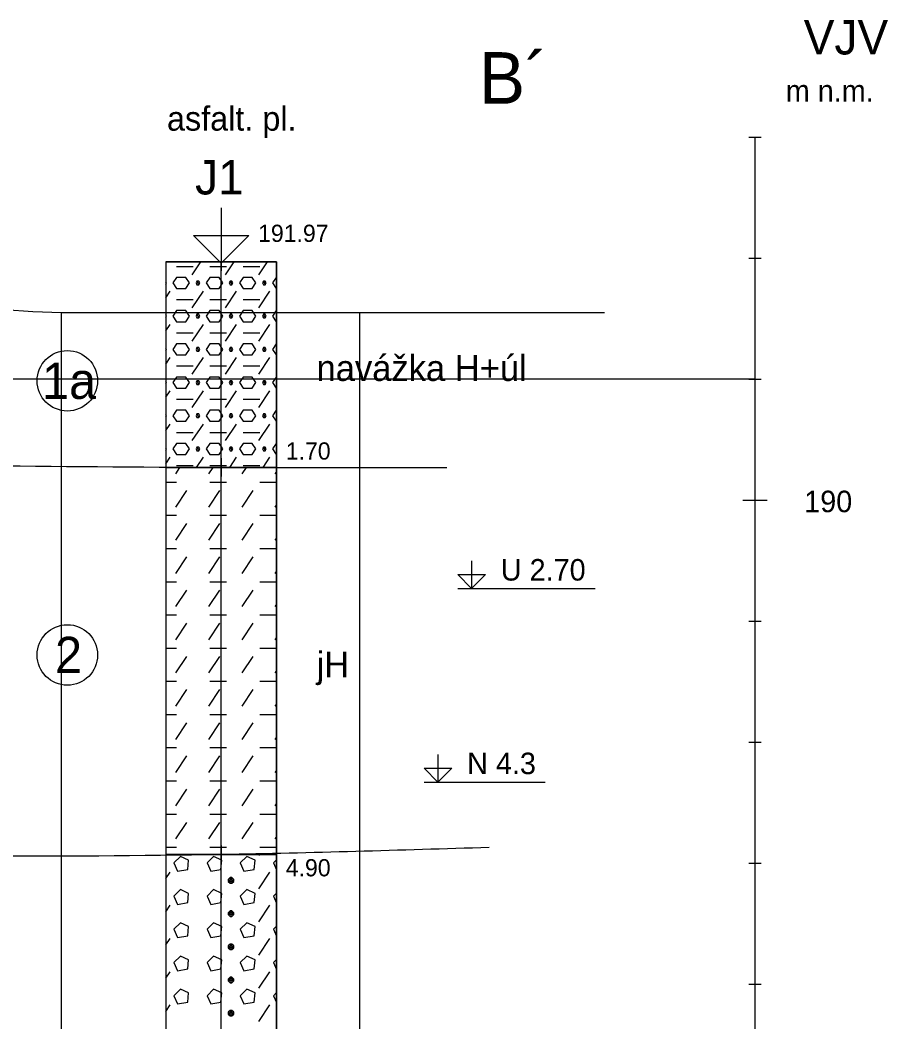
# Model space of a CAD drawing. Extents: x 3042 to 4120, y 576 to 2694.
# Drawn here: x 3544.48 to 3580.33, y 1143.21 to 1184.62 of the extents above; entities that cross this region are included whole.
import ezdxf

# ---------------------------------------------------------------- set-up
doc = ezdxf.new("R2010")
doc.units = 0
for name, color, linetype in [('15', 7, 'Continuous'), ('16', 7, 'Continuous'), ('17', 7, 'Continuous'), ('18', 7, 'Continuous'), ('19', 7, 'Continuous'), ('20', 7, 'Continuous'), ('21', 7, 'Continuous'), ('51', 7, 'Continuous'), ('52', 7, 'Continuous'), ('53', 7, 'Continuous'), ('56', 7, 'Continuous'), ('61', 7, 'Continuous'), ('ig vrty popis', 7, 'Continuous'), ('komunikace', 7, 'Continuous'), ('pomocna', 7, 'Continuous'), ('rozhraní', 7, 'Continuous')]:
    doc.layers.add(name, color=color, linetype=linetype)

msp = doc.modelspace()

# ---------------------------------------------------------------- linework, layer by layer
at = {"layer": '15'}
msp.add_lwpolyline([(3552.792, 1176.852), (3552.792, 1174.566), (3551.649, 1175.709), (3553.935, 1175.709), (3552.792, 1174.566)], dxfattribs=at)
at = {"layer": '18'}
msp.add_line((3552.792, 1134.629), (3552.792, 1174.629), dxfattribs=at)
at = {"layer": '19'}
for p, q in [((3574.588, 1179.779), (3575.096, 1179.779)), ((3574.588, 1174.779), (3575.096, 1174.779)), ((3574.588, 1169.779), (3575.096, 1169.779)), ((3574.334, 1164.779), (3575.35, 1164.779)), ((3574.588, 1159.779), (3575.096, 1159.779)), ((3574.588, 1154.779), (3575.096, 1154.779)), ((3574.588, 1149.779), (3575.096, 1149.779)), ((3574.588, 1144.779), (3575.096, 1144.779))]:
    msp.add_line(p, q, dxfattribs=at)
at = {"layer": '21'}
msp.add_line((3574.842, 1114.779), (3574.842, 1179.779), dxfattribs=at)
at = {"layer": '51'}
for p, q in [((3551.598, 1174.093), (3551.955, 1174.629)), ((3552.97, 1174.093), (3553.327, 1174.629)), ((3554.342, 1174.093), (3554.699, 1174.629)), ((3550.951, 1174.436), (3551.636, 1174.436)), ((3552.322, 1174.436), (3553.008, 1174.436)), ((3553.694, 1174.436), (3554.38, 1174.436)), ((3555.065, 1174.436), (3555.078, 1174.436)), ((3550.506, 1173.14), (3550.684, 1173.408)), ((3551.598, 1172.722), (3552.055, 1173.408)), ((3552.97, 1172.722), (3553.427, 1173.408)), ((3554.342, 1172.722), (3554.799, 1173.408)), ((3555.065, 1173.522), (3555.078, 1173.522)), ((3550.951, 1173.065), (3551.636, 1173.065)), ((3552.322, 1173.065), (3553.008, 1173.065)), ((3553.694, 1173.065), (3554.38, 1173.065)), ((3555.065, 1173.065), (3555.078, 1173.065)), ((3555.065, 1172.15), (3555.078, 1172.15)), ((3550.506, 1171.769), (3550.684, 1172.036)), ((3550.951, 1171.693), (3551.636, 1171.693)), ((3551.598, 1171.35), (3552.055, 1172.036)), ((3552.322, 1171.693), (3553.008, 1171.693)), ((3552.97, 1171.35), (3553.427, 1172.036)), ((3553.694, 1171.693), (3554.38, 1171.693)), ((3554.342, 1171.35), (3554.799, 1172.036)), ((3555.065, 1171.693), (3555.078, 1171.693)), ((3550.506, 1170.397), (3550.684, 1170.664)), ((3551.598, 1169.979), (3552.055, 1170.664)), ((3552.97, 1169.979), (3553.427, 1170.664)), ((3554.342, 1169.979), (3554.799, 1170.664)), ((3555.065, 1170.779), (3555.078, 1170.779)), ((3550.951, 1170.322), (3551.636, 1170.322)), ((3552.322, 1170.322), (3553.008, 1170.322)), ((3553.694, 1170.322), (3554.38, 1170.322)), ((3555.065, 1170.322), (3555.078, 1170.322)), ((3550.506, 1169.026), (3550.684, 1169.293)), ((3551.598, 1168.607), (3552.055, 1169.293)), ((3552.97, 1168.607), (3553.427, 1169.293)), ((3554.342, 1168.607), (3554.799, 1169.293)), ((3555.065, 1169.407), (3555.078, 1169.407)), ((3550.951, 1168.95), (3551.636, 1168.95)), ((3552.322, 1168.95), (3553.008, 1168.95)), ((3553.694, 1168.95), (3554.38, 1168.95)), ((3555.065, 1168.95), (3555.078, 1168.95)), ((3555.065, 1168.036), (3555.078, 1168.036)), ((3550.506, 1167.654), (3550.684, 1167.921)), ((3550.951, 1167.578), (3551.636, 1167.578)), ((3551.598, 1167.235), (3552.055, 1167.921)), ((3552.322, 1167.578), (3553.008, 1167.578)), ((3552.97, 1167.235), (3553.427, 1167.921)), ((3553.694, 1167.578), (3554.38, 1167.578)), ((3554.342, 1167.235), (3554.799, 1167.921)), ((3555.065, 1167.578), (3555.078, 1167.578)), ((3550.506, 1166.282), (3550.684, 1166.55)), ((3551.775, 1166.129), (3552.055, 1166.55)), ((3553.147, 1166.129), (3553.427, 1166.55)), ((3554.518, 1166.129), (3554.799, 1166.55)), ((3555.065, 1166.664), (3555.078, 1166.664)), ((3550.912, 1165.864), (3551.089, 1166.129)), ((3550.951, 1166.207), (3551.636, 1166.207)), ((3552.284, 1165.864), (3552.461, 1166.129)), ((3552.322, 1166.207), (3553.008, 1166.207)), ((3553.656, 1165.864), (3553.833, 1166.129)), ((3553.694, 1166.207), (3554.38, 1166.207)), ((3555.027, 1165.864), (3555.078, 1165.939)), ((3555.065, 1166.207), (3555.078, 1166.207)), ((3550.506, 1165.521), (3550.951, 1165.521)), ((3552.322, 1165.521), (3553.008, 1165.521)), ((3554.38, 1165.521), (3555.065, 1165.521)), ((3550.912, 1164.492), (3551.37, 1165.178)), ((3552.284, 1164.492), (3552.741, 1165.178)), ((3553.656, 1164.492), (3554.113, 1165.178)), ((3555.027, 1164.492), (3555.078, 1164.568)), ((3550.506, 1164.149), (3550.951, 1164.149)), ((3552.322, 1164.149), (3553.008, 1164.149)), ((3554.38, 1164.149), (3555.065, 1164.149)), ((3550.912, 1163.121), (3551.37, 1163.806)), ((3552.284, 1163.121), (3552.741, 1163.806)), ((3553.656, 1163.121), (3554.113, 1163.806)), ((3555.027, 1163.121), (3555.078, 1163.196)), ((3550.506, 1162.778), (3550.951, 1162.778)), ((3552.322, 1162.778), (3553.008, 1162.778)), ((3554.38, 1162.778), (3555.065, 1162.778)), ((3550.912, 1161.749), (3551.37, 1162.435)), ((3552.284, 1161.749), (3552.741, 1162.435)), ((3553.656, 1161.749), (3554.113, 1162.435)), ((3555.027, 1161.749), (3555.078, 1161.825)), ((3550.506, 1161.406), (3550.951, 1161.406)), ((3552.322, 1161.406), (3553.008, 1161.406)), ((3554.38, 1161.406), (3555.065, 1161.406)), ((3550.912, 1160.377), (3551.37, 1161.063)), ((3552.284, 1160.377), (3552.741, 1161.063)), ((3553.656, 1160.377), (3554.113, 1161.063)), ((3555.027, 1160.377), (3555.078, 1160.453)), ((3550.506, 1160.035), (3550.951, 1160.035)), ((3550.912, 1159.006), (3551.37, 1159.692)), ((3552.284, 1159.006), (3552.741, 1159.692)), ((3552.322, 1160.035), (3553.008, 1160.035)), ((3553.656, 1159.006), (3554.113, 1159.692)), ((3554.38, 1160.035), (3555.065, 1160.035)), ((3555.027, 1159.006), (3555.078, 1159.081)), ((3550.506, 1158.663), (3550.951, 1158.663)), ((3552.322, 1158.663), (3553.008, 1158.663)), ((3554.38, 1158.663), (3555.065, 1158.663)), ((3550.912, 1157.634), (3551.37, 1158.32)), ((3552.284, 1157.634), (3552.741, 1158.32)), ((3553.656, 1157.634), (3554.113, 1158.32)), ((3555.027, 1157.634), (3555.078, 1157.71)), ((3550.506, 1157.291), (3550.951, 1157.291)), ((3552.322, 1157.291), (3553.008, 1157.291)), ((3554.38, 1157.291), (3555.065, 1157.291)), ((3550.912, 1156.263), (3551.37, 1156.948)), ((3552.284, 1156.263), (3552.741, 1156.948)), ((3553.656, 1156.263), (3554.113, 1156.948)), ((3555.027, 1156.263), (3555.078, 1156.338)), ((3550.506, 1155.92), (3550.951, 1155.92)), ((3550.912, 1154.891), (3551.37, 1155.577)), ((3552.284, 1154.891), (3552.741, 1155.577)), ((3552.322, 1155.92), (3553.008, 1155.92)), ((3553.656, 1154.891), (3554.113, 1155.577)), ((3554.38, 1155.92), (3555.065, 1155.92)), ((3555.027, 1154.891), (3555.078, 1154.967)), ((3550.506, 1154.548), (3550.951, 1154.548)), ((3552.322, 1154.548), (3553.008, 1154.548)), ((3554.38, 1154.548), (3555.065, 1154.548)), ((3550.912, 1153.519), (3551.37, 1154.205)), ((3552.284, 1153.519), (3552.741, 1154.205)), ((3553.656, 1153.519), (3554.113, 1154.205)), ((3555.027, 1153.519), (3555.078, 1153.595)), ((3550.506, 1153.177), (3550.951, 1153.177)), ((3552.322, 1153.177), (3553.008, 1153.177)), ((3554.38, 1153.177), (3555.065, 1153.177)), ((3550.912, 1152.148), (3551.37, 1152.834)), ((3552.284, 1152.148), (3552.741, 1152.834)), ((3553.656, 1152.148), (3554.113, 1152.834)), ((3555.027, 1152.148), (3555.078, 1152.223)), ((3550.506, 1151.805), (3550.951, 1151.805)), ((3552.322, 1151.805), (3553.008, 1151.805)), ((3554.38, 1151.805), (3555.065, 1151.805)), ((3550.912, 1150.776), (3551.37, 1151.462)), ((3552.284, 1150.776), (3552.741, 1151.462)), ((3553.656, 1150.776), (3554.113, 1151.462)), ((3555.027, 1150.776), (3555.078, 1150.852)), ((3550.506, 1150.433), (3550.951, 1150.433)), ((3552.322, 1150.433), (3553.008, 1150.433)), ((3554.38, 1150.433), (3555.065, 1150.433)), ((3554.342, 1150.09), (3554.367, 1150.129)), ((3555.078, 1149.912), (3554.951, 1149.786)), ((3554.951, 1149.786), (3555.078, 1149.501)), ((3550.506, 1149.137), (3550.684, 1149.405)), ((3554.342, 1148.719), (3554.799, 1149.405)), ((3553.198, 1148.947), (3553.198, 1149.176)), ((3555.078, 1148.541), (3554.951, 1148.414)), ((3554.951, 1148.414), (3555.078, 1148.129)), ((3550.506, 1147.766), (3550.684, 1148.033)), ((3553.198, 1147.576), (3553.198, 1147.804)), ((3554.342, 1147.347), (3554.799, 1148.033)), ((3555.078, 1147.169), (3554.951, 1147.042)), ((3554.951, 1147.042), (3555.078, 1146.758)), ((3550.506, 1146.394), (3550.684, 1146.661)), ((3553.198, 1146.204), (3553.198, 1146.433)), ((3554.342, 1145.976), (3554.799, 1146.661)), ((3555.078, 1145.797), (3554.951, 1145.671)), ((3554.951, 1145.671), (3555.078, 1145.386)), ((3550.506, 1145.023), (3550.684, 1145.29)), ((3554.342, 1144.604), (3554.799, 1145.29)), ((3553.198, 1144.833), (3553.198, 1145.061)), ((3555.078, 1144.426), (3554.951, 1144.299)), ((3554.951, 1144.299), (3555.078, 1144.014)), ((3550.506, 1143.651), (3550.684, 1143.918)), ((3553.198, 1143.461), (3553.198, 1143.69)), ((3554.342, 1143.232), (3554.799, 1143.918))]:
    msp.add_line(p, q, dxfattribs=at)
for points in [[(3550.506, 1166.129), (3555.078, 1166.129), (3555.078, 1174.629), (3550.506, 1174.629)], [(3550.506, 1150.129), (3555.078, 1150.129), (3555.078, 1166.129), (3550.506, 1166.129)], [(3550.506, 1134.629), (3555.078, 1134.629), (3555.078, 1150.129), (3550.506, 1150.129)]]:
    msp.add_lwpolyline(points, close=True, dxfattribs=at)
for points in [[(3550.506, 1173.699), (3550.531, 1173.751), (3550.506, 1173.802)], [(3550.951, 1173.522), (3551.332, 1173.522), (3551.484, 1173.751), (3551.332, 1173.979), (3550.951, 1173.979), (3550.798, 1173.751), (3550.951, 1173.522)], [(3551.789, 1173.827), (3551.751, 1173.751), (3551.789, 1173.674), (3551.865, 1173.674), (3551.903, 1173.751), (3551.865, 1173.827), (3551.789, 1173.827), (3551.865, 1173.674)], [(3552.322, 1173.522), (3552.703, 1173.522), (3552.856, 1173.751), (3552.703, 1173.979), (3552.322, 1173.979), (3552.17, 1173.751), (3552.322, 1173.522)], [(3553.16, 1173.827), (3553.122, 1173.751), (3553.16, 1173.674), (3553.237, 1173.674), (3553.275, 1173.751), (3553.237, 1173.827), (3553.16, 1173.827), (3553.237, 1173.674)], [(3553.694, 1173.522), (3554.075, 1173.522), (3554.227, 1173.751), (3554.075, 1173.979), (3553.694, 1173.979), (3553.541, 1173.751), (3553.694, 1173.522)], [(3554.532, 1173.827), (3554.494, 1173.751), (3554.532, 1173.674), (3554.608, 1173.674), (3554.646, 1173.751), (3554.608, 1173.827), (3554.532, 1173.827), (3554.608, 1173.674)], [(3555.078, 1173.979), (3555.065, 1173.979), (3554.913, 1173.751), (3555.065, 1173.522)], [(3550.951, 1172.15), (3551.332, 1172.15), (3551.484, 1172.379), (3551.332, 1172.608), (3550.951, 1172.608), (3550.798, 1172.379), (3550.951, 1172.15)], [(3552.322, 1172.15), (3552.703, 1172.15), (3552.856, 1172.379), (3552.703, 1172.608), (3552.322, 1172.608), (3552.17, 1172.379), (3552.322, 1172.15)], [(3553.694, 1172.15), (3554.075, 1172.15), (3554.227, 1172.379), (3554.075, 1172.608), (3553.694, 1172.608), (3553.541, 1172.379), (3553.694, 1172.15)], [(3555.078, 1172.608), (3555.065, 1172.608), (3554.913, 1172.379), (3555.065, 1172.15)], [(3550.506, 1172.327), (3550.531, 1172.379), (3550.506, 1172.43)], [(3551.789, 1172.455), (3551.751, 1172.379), (3551.789, 1172.303), (3551.865, 1172.303), (3551.903, 1172.379), (3551.865, 1172.455), (3551.789, 1172.455), (3551.865, 1172.303)], [(3553.16, 1172.455), (3553.122, 1172.379), (3553.16, 1172.303), (3553.237, 1172.303), (3553.275, 1172.379), (3553.237, 1172.455), (3553.16, 1172.455), (3553.237, 1172.303)], [(3554.532, 1172.455), (3554.494, 1172.379), (3554.532, 1172.303), (3554.608, 1172.303), (3554.646, 1172.379), (3554.608, 1172.455), (3554.532, 1172.455), (3554.608, 1172.303)], [(3550.506, 1170.956), (3550.531, 1171.007), (3550.506, 1171.059)], [(3550.951, 1170.779), (3551.332, 1170.779), (3551.484, 1171.007), (3551.332, 1171.236), (3550.951, 1171.236), (3550.798, 1171.007), (3550.951, 1170.779)], [(3551.789, 1171.084), (3551.751, 1171.007), (3551.789, 1170.931), (3551.865, 1170.931), (3551.903, 1171.007), (3551.865, 1171.084), (3551.789, 1171.084), (3551.865, 1170.931)], [(3552.322, 1170.779), (3552.703, 1170.779), (3552.856, 1171.007), (3552.703, 1171.236), (3552.322, 1171.236), (3552.17, 1171.007), (3552.322, 1170.779)], [(3553.16, 1171.084), (3553.122, 1171.007), (3553.16, 1170.931), (3553.237, 1170.931), (3553.275, 1171.007), (3553.237, 1171.084), (3553.16, 1171.084), (3553.237, 1170.931)], [(3553.694, 1170.779), (3554.075, 1170.779), (3554.227, 1171.007), (3554.075, 1171.236), (3553.694, 1171.236), (3553.541, 1171.007), (3553.694, 1170.779)], [(3554.532, 1171.084), (3554.494, 1171.007), (3554.532, 1170.931), (3554.608, 1170.931), (3554.646, 1171.007), (3554.608, 1171.084), (3554.532, 1171.084), (3554.608, 1170.931)], [(3555.078, 1171.236), (3555.065, 1171.236), (3554.913, 1171.007), (3555.065, 1170.779)], [(3550.506, 1169.584), (3550.531, 1169.636), (3550.506, 1169.687)], [(3550.951, 1169.407), (3551.332, 1169.407), (3551.484, 1169.636), (3551.332, 1169.864), (3550.951, 1169.864), (3550.798, 1169.636), (3550.951, 1169.407)], [(3551.789, 1169.712), (3551.751, 1169.636), (3551.789, 1169.56), (3551.865, 1169.56), (3551.903, 1169.636), (3551.865, 1169.712), (3551.789, 1169.712), (3551.865, 1169.56)], [(3552.322, 1169.407), (3552.703, 1169.407), (3552.856, 1169.636), (3552.703, 1169.864), (3552.322, 1169.864), (3552.17, 1169.636), (3552.322, 1169.407)], [(3553.16, 1169.712), (3553.122, 1169.636), (3553.16, 1169.56), (3553.237, 1169.56), (3553.275, 1169.636), (3553.237, 1169.712), (3553.16, 1169.712), (3553.237, 1169.56)], [(3553.694, 1169.407), (3554.075, 1169.407), (3554.227, 1169.636), (3554.075, 1169.864), (3553.694, 1169.864), (3553.541, 1169.636), (3553.694, 1169.407)], [(3554.532, 1169.712), (3554.494, 1169.636), (3554.532, 1169.56), (3554.608, 1169.56), (3554.646, 1169.636), (3554.608, 1169.712), (3554.532, 1169.712), (3554.608, 1169.56)], [(3555.078, 1169.864), (3555.065, 1169.864), (3554.913, 1169.636), (3555.065, 1169.407)], [(3550.951, 1168.036), (3551.332, 1168.036), (3551.484, 1168.264), (3551.332, 1168.493), (3550.951, 1168.493), (3550.798, 1168.264), (3550.951, 1168.036)], [(3552.322, 1168.036), (3552.703, 1168.036), (3552.856, 1168.264), (3552.703, 1168.493), (3552.322, 1168.493), (3552.17, 1168.264), (3552.322, 1168.036)], [(3553.694, 1168.036), (3554.075, 1168.036), (3554.227, 1168.264), (3554.075, 1168.493), (3553.694, 1168.493), (3553.541, 1168.264), (3553.694, 1168.036)], [(3555.078, 1168.493), (3555.065, 1168.493), (3554.913, 1168.264), (3555.065, 1168.036)], [(3550.506, 1168.213), (3550.531, 1168.264), (3550.506, 1168.316)], [(3551.789, 1168.34), (3551.751, 1168.264), (3551.789, 1168.188), (3551.865, 1168.188), (3551.903, 1168.264), (3551.865, 1168.34), (3551.789, 1168.34), (3551.865, 1168.188)], [(3553.16, 1168.34), (3553.122, 1168.264), (3553.16, 1168.188), (3553.237, 1168.188), (3553.275, 1168.264), (3553.237, 1168.34), (3553.16, 1168.34), (3553.237, 1168.188)], [(3554.532, 1168.34), (3554.494, 1168.264), (3554.532, 1168.188), (3554.608, 1168.188), (3554.646, 1168.264), (3554.608, 1168.34), (3554.532, 1168.34), (3554.608, 1168.188)], [(3550.506, 1166.841), (3550.531, 1166.893), (3550.506, 1166.944)], [(3550.951, 1166.664), (3551.332, 1166.664), (3551.484, 1166.893), (3551.332, 1167.121), (3550.951, 1167.121), (3550.798, 1166.893), (3550.951, 1166.664)], [(3551.789, 1166.969), (3551.751, 1166.893), (3551.789, 1166.816), (3551.865, 1166.816), (3551.903, 1166.893), (3551.865, 1166.969), (3551.789, 1166.969), (3551.865, 1166.816)], [(3552.322, 1166.664), (3552.703, 1166.664), (3552.856, 1166.893), (3552.703, 1167.121), (3552.322, 1167.121), (3552.17, 1166.893), (3552.322, 1166.664)], [(3553.16, 1166.969), (3553.122, 1166.893), (3553.16, 1166.816), (3553.237, 1166.816), (3553.275, 1166.893), (3553.237, 1166.969), (3553.16, 1166.969), (3553.237, 1166.816)], [(3553.694, 1166.664), (3554.075, 1166.664), (3554.227, 1166.893), (3554.075, 1167.121), (3553.694, 1167.121), (3553.541, 1166.893), (3553.694, 1166.664)], [(3554.532, 1166.969), (3554.494, 1166.893), (3554.532, 1166.816), (3554.608, 1166.816), (3554.646, 1166.893), (3554.608, 1166.969), (3554.532, 1166.969), (3554.608, 1166.816)], [(3555.078, 1167.121), (3555.065, 1167.121), (3554.913, 1166.893), (3555.065, 1166.664)], [(3550.836, 1149.786), (3550.989, 1149.443), (3551.408, 1149.519), (3551.446, 1149.9), (3551.103, 1150.052), (3550.836, 1149.786)], [(3552.208, 1149.786), (3552.36, 1149.443), (3552.779, 1149.519), (3552.817, 1149.9), (3552.475, 1150.052), (3552.208, 1149.786)], [(3553.579, 1149.786), (3553.732, 1149.443), (3554.151, 1149.519), (3554.189, 1149.9), (3553.846, 1150.052), (3553.579, 1149.786)], [(3553.16, 1149.176), (3553.084, 1149.1), (3553.084, 1149.024), (3553.16, 1148.947), (3553.237, 1148.947), (3553.313, 1149.024), (3553.313, 1149.1), (3553.237, 1149.176), (3553.16, 1149.176), (3553.313, 1149.024), (3553.084, 1149.024), (3553.237, 1149.176)], [(3550.836, 1148.414), (3550.989, 1148.071), (3551.408, 1148.147), (3551.446, 1148.528), (3551.103, 1148.681), (3550.836, 1148.414)], [(3552.208, 1148.414), (3552.36, 1148.071), (3552.779, 1148.147), (3552.817, 1148.528), (3552.475, 1148.681), (3552.208, 1148.414)], [(3553.579, 1148.414), (3553.732, 1148.071), (3554.151, 1148.147), (3554.189, 1148.528), (3553.846, 1148.681), (3553.579, 1148.414)], [(3553.16, 1147.804), (3553.084, 1147.728), (3553.084, 1147.652), (3553.16, 1147.576), (3553.237, 1147.576), (3553.313, 1147.652), (3553.313, 1147.728), (3553.237, 1147.804), (3553.16, 1147.804), (3553.313, 1147.652), (3553.084, 1147.652), (3553.237, 1147.804)], [(3550.836, 1147.042), (3550.989, 1146.7), (3551.408, 1146.776), (3551.446, 1147.157), (3551.103, 1147.309), (3550.836, 1147.042)], [(3552.208, 1147.042), (3552.36, 1146.7), (3552.779, 1146.776), (3552.817, 1147.157), (3552.475, 1147.309), (3552.208, 1147.042)], [(3553.579, 1147.042), (3553.732, 1146.7), (3554.151, 1146.776), (3554.189, 1147.157), (3553.846, 1147.309), (3553.579, 1147.042)], [(3553.16, 1146.433), (3553.084, 1146.357), (3553.084, 1146.28), (3553.16, 1146.204), (3553.237, 1146.204), (3553.313, 1146.28), (3553.313, 1146.357), (3553.237, 1146.433), (3553.16, 1146.433), (3553.313, 1146.28), (3553.084, 1146.28), (3553.237, 1146.433)], [(3550.836, 1145.671), (3550.989, 1145.328), (3551.408, 1145.404), (3551.446, 1145.785), (3551.103, 1145.938), (3550.836, 1145.671)], [(3552.208, 1145.671), (3552.36, 1145.328), (3552.779, 1145.404), (3552.817, 1145.785), (3552.475, 1145.938), (3552.208, 1145.671)], [(3553.579, 1145.671), (3553.732, 1145.328), (3554.151, 1145.404), (3554.189, 1145.785), (3553.846, 1145.938), (3553.579, 1145.671)], [(3553.16, 1145.061), (3553.084, 1144.985), (3553.084, 1144.909), (3553.16, 1144.833), (3553.237, 1144.833), (3553.313, 1144.909), (3553.313, 1144.985), (3553.237, 1145.061), (3553.16, 1145.061), (3553.313, 1144.909), (3553.084, 1144.909), (3553.237, 1145.061)], [(3550.836, 1144.299), (3550.989, 1143.956), (3551.408, 1144.033), (3551.446, 1144.414), (3551.103, 1144.566), (3550.836, 1144.299)], [(3552.208, 1144.299), (3552.36, 1143.956), (3552.779, 1144.033), (3552.817, 1144.414), (3552.475, 1144.566), (3552.208, 1144.299)], [(3553.579, 1144.299), (3553.732, 1143.956), (3554.151, 1144.033), (3554.189, 1144.414), (3553.846, 1144.566), (3553.579, 1144.299)], [(3553.16, 1143.69), (3553.084, 1143.613), (3553.084, 1143.537), (3553.16, 1143.461), (3553.237, 1143.461), (3553.313, 1143.537), (3553.313, 1143.613), (3553.237, 1143.69), (3553.16, 1143.69), (3553.313, 1143.537), (3553.084, 1143.537), (3553.237, 1143.69)]]:
    msp.add_lwpolyline(points, dxfattribs=at)
at = {"layer": '53'}
for p, q in [((3550.506, 1174.629), (3555.078, 1174.629)), ((3550.506, 1174.629), (3550.506, 1134.629)), ((3555.078, 1174.629), (3555.078, 1134.629)), ((3550.506, 1166.129), (3555.078, 1166.129)), ((3550.506, 1150.129), (3555.078, 1150.129))]:
    msp.add_line(p, q, dxfattribs=at)
at = {"layer": '56'}
for p, q in [((3552.792, 1175.01), (3552.792, 1174.248)), ((3552.411, 1174.629), (3553.173, 1174.629)), ((3552.792, 1166.51), (3552.792, 1165.748)), ((3552.411, 1166.129), (3553.173, 1166.129)), ((3552.792, 1150.51), (3552.792, 1149.748)), ((3552.411, 1150.129), (3553.173, 1150.129))]:
    msp.add_line(p, q, dxfattribs=at)
at = {"layer": '61'}
for p, q in [((3562.564, 1161.129), (3568.237, 1161.129)), ((3561.171, 1153.129), (3566.167, 1153.129))]:
    msp.add_line(p, q, dxfattribs=at)
for points in [[(3563.136, 1162.272), (3563.136, 1161.129), (3562.564, 1161.701), (3563.707, 1161.701), (3563.136, 1161.129)], [(3561.743, 1154.272), (3561.743, 1153.129), (3561.171, 1153.701), (3562.314, 1153.701), (3561.743, 1153.129)]]:
    msp.add_lwpolyline(points, dxfattribs=at)
at = {"layer": 'komunikace'}
msp.add_line((3546.192, 1172.529), (3558.522, 1172.529), dxfattribs=at)
at = {"layer": 'pomocna'}
for p, q in [((3546.192, 1114.398), (3546.192, 1172.529)), ((3547.354, 1172.529), (3568.624, 1172.529)), ((3552.792, 1114.398), (3552.792, 1172.898)), ((3558.522, 1114.398), (3558.522, 1172.529)), ((3574.842, 1169.779), (3535.181, 1169.779))]:
    msp.add_line(p, q, dxfattribs=at)
at = {"layer": 'rozhraní'}
for centre in [(3546.436, 1169.709), (3546.436, 1158.379)]:
    msp.add_circle(centre, 1.25, dxfattribs=at)
for points in [[(3539.912, 1173.129), (3546.192, 1172.529), (3547.354, 1172.529)], [(3532.339, 1166.362), (3552.792, 1166.129), (3562.109, 1166.129)], [(3563.861, 1150.423), (3552.84, 1150.129), (3532.396, 1150.129)]]:
    msp.add_spline(points, degree=3, dxfattribs=at)

# ---------------------------------------------------------------- texts
at = {"layer": '16'}
msp.add_text('J1', height=1.4224, dxfattribs=at).set_placement((3551.712, 1177.408))
at = {"layer": '17'}
msp.add_text('191.97', height=0.7112, dxfattribs=at).set_placement((3554.316, 1175.447))
at = {"layer": '19'}
for s, p in [('m n.m.', (3576.112, 1181.246)), ('190', (3576.874, 1164.278))]:
    msp.add_text(s, height=0.889, dxfattribs=at).set_placement(p)
at = {"layer": '20'}
msp.add_text('VJV', height=1.4224, dxfattribs=at).set_placement((3576.853, 1183.193))
at = {"layer": '52'}
for s, height, p in [('navážka H+úl', 1.0668, (3556.729, 1169.701)), ('1.70', 0.7112, (3555.459, 1166.452)), ('jH', 1.0668, (3556.729, 1157.451)), ('4.90', 0.7112, (3555.459, 1149.231))]:
    msp.add_text(s, height=height, dxfattribs=at).set_placement(p)
at = {"layer": '61'}
for s, p in [('U 2.70', (3564.342, 1161.453)), ('N 4.3', (3562.949, 1153.453))]:
    msp.add_text(s, height=0.889, dxfattribs=at).set_placement(p)
at = {"layer": 'ig vrty popis'}
msp.add_text('B´', height=2.132, dxfattribs=at).set_placement((3563.441, 1181.156))
at = {"layer": 'komunikace'}
msp.add_text('asfalt. pl.', height=1, dxfattribs=at).set_placement((3550.551, 1180.044))
at = {"layer": 'rozhraní'}
for s, p in [('1a', (3545.393, 1168.959)), ('2', (3545.928, 1157.629))]:
    msp.add_text(s, height=1.5, dxfattribs=at).set_placement(p)

doc.saveas('drawing.dxf')
